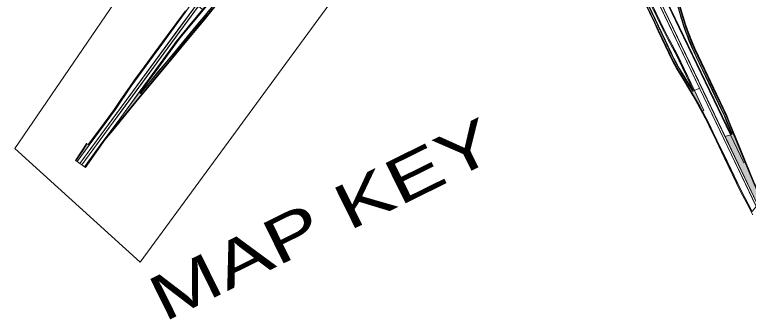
# Model space of a CAD drawing. Extents: x 2356431 to 2371438, y 6972864 to 6982525.
# Drawn here: x 2357864 to 2358220.2, y 6974139.1 to 6974287.2 of the extents above; entities that cross this region are included whole.
import ezdxf

# ---------------------------------------------------------------- set-up
doc = ezdxf.new("R2010")
doc.units = 0
doc.header["$LTSCALE"] = 5.6
for name, color, linetype, lineweight in [('1', 7, 'Continuous', 25), ('10', 7, 'Continuous', 13), ('11', 7, 'Continuous', 13), ('12', 7, 'Continuous', 13), ('13', 7, 'Continuous', 13), ('62', 7, 'Continuous', 25)]:
    doc.layers.add(name, color=color, linetype=linetype, lineweight=lineweight)

msp = doc.modelspace()

# ---------------------------------------------------------------- hatches: boundary and pattern name
at = {"layer": '10'}
for points in [[(2358224.717, 6974194.96), (2358208.937, 6974227.964), (2358211.515, 6974228.83), (2358218.055, 6974215.176), (2358218.638, 6974215.414), (2358222.665, 6974205.55), (2358226.597, 6974197.381)], [(2357893.563, 6974216.383), (2357895.685, 6974219.575), (2357897.226, 6974221.919), (2357898.834, 6974224.657), (2357899.065, 6974224.514), (2357897.698, 6974222.187), (2357896.333, 6974220.089), (2357893.792, 6974216.21)]]:
    msp.add_hatch(color=256, dxfattribs=at).paths.add_polyline_path(points)
at = {"layer": '11'}
for points in [[(2357925.7, 6974248.581), (2357924.467, 6974249.487), (2357915.516, 6974237.29), (2357906.867, 6974225.616)], [(2357899.657, 6974224.163), (2357899.663, 6974224.236), (2357899.684, 6974224.061), (2357900.231, 6974223.779), (2357894.37, 6974215.806), (2357893.782, 6974216.225), (2357895.973, 6974219.512), (2357897.045, 6974221.146), (2357897.88, 6974222.577), (2357898.671, 6974223.818), (2357899.091, 6974224.462)]]:
    msp.add_hatch(color=256, dxfattribs=at).paths.add_polyline_path(points)
at = {"layer": '12'}
msp.add_hatch(color=256, dxfattribs=at).paths.add_polyline_path([(2358190.807, 6974276.108), (2358191.907, 6974276.508), (2358191.955, 6974276.382), (2358190.848, 6974275.981)])
at = {"layer": '13'}
for points in [[(2358188.092, 6974284.474), (2358186.811, 6974288.798), (2358185.541, 6974293.103), (2358184.275, 6974297.396), (2358183.011, 6974301.686), (2358181.658, 6974306.215), (2358180.443, 6974310.36), (2358179.165, 6974314.68), (2358177.844, 6974319.167), (2358178.47, 6974319.318), (2358179.711, 6974314.999), (2358181.042, 6974310.533), (2358182.32, 6974306.211), (2358183.579, 6974301.919), (2358184.842, 6974297.591), (2358186.152, 6974293.285), (2358187.409, 6974288.971), (2358188.697, 6974284.671)], [(2358191.615, 6974276.261), (2358190.083, 6974280.403), (2358188.697, 6974284.671), (2358188.092, 6974284.474), (2358189.441, 6974280.321), (2358190.097, 6974278.481), (2358191.018, 6974276.049)], [(2358206.849, 6974243.48), (2358204.316, 6974248.759), (2358202.039, 6974253.505), (2358200.843, 6974256.042), (2358199.706, 6974258.405), (2358198.739, 6974260.444), (2358198.431, 6974261.097), (2358197.262, 6974263.526), (2358196.947, 6974264.198), (2358194.587, 6974269.146), (2358193.682, 6974271.143), (2358192.779, 6974273.301), (2358191.615, 6974276.261), (2358191.018, 6974276.049), (2358191.605, 6974274.534), (2358192.487, 6974272.368), (2358194.056, 6974268.828), (2358194.955, 6974266.891), (2358197.368, 6974261.863), (2358199.857, 6974256.62), (2358201.785, 6974252.602), (2358204.121, 6974247.695), (2358205.16, 6974245.532), (2358207.016, 6974241.658), (2358208.14, 6974239.202), (2358208.739, 6974239.437)], [(2358187.364, 6974258.405), (2358189.116, 6974255.565), (2358192.039, 6974250.69), (2358194.6, 6974246.247), (2358196.629, 6974242.689), (2358197.823, 6974240.502), (2358197.918, 6974240.283), (2358198.657, 6974240.628), (2358194.012, 6974250.377), (2358193.192, 6974249.987), (2358190.49, 6974254.441), (2358187.921, 6974258.702)], [(2358208.14, 6974239.202), (2358208.77, 6974237.788), (2358209.583, 6974235.939), (2358210.039, 6974234.811), (2358212.325, 6974229.219), (2358211.515, 6974228.83), (2358218.055, 6974215.176), (2358218.638, 6974215.414), (2358212.882, 6974229.514), (2358210.848, 6974234.505), (2358209.364, 6974238.035), (2358208.739, 6974239.437)]]:
    msp.add_hatch(color=256, dxfattribs=at).paths.add_polyline_path(points)

# ---------------------------------------------------------------- linework, layer by layer
at = {"layer": '1', "lineweight": 13}
msp.add_lwpolyline([(2357864.034, 6974222.186), (2358026.863, 6974460.681), (2358031.311, 6974671.634), (2358108.425, 6974690.15), (2358128.625, 6974445.163), (2357925.008, 6974166.994)], close=True, dxfattribs=at)
at = {"layer": '10'}
for points in [[(2358010.915, 6974373.717), (2358012.268, 6974375.13), (2358013.679, 6974376.599), (2358016.224, 6974379.189), (2358007.461, 6974367.185), (2358000.024, 6974357.06), (2357895.642, 6974214.803), (2357894.37, 6974215.806), (2357900.231, 6974223.779), (2357912.964, 6974241.147), (2357920.525, 6974252.361), (2357946.84, 6974288.246), (2357953.979, 6974298.419), (2357959.607, 6974307.178), (2357960.598, 6974306.665), (2357961.331, 6974306.146)], [(2358223.989, 6974194.055), (2358141.811, 6974365.622), (2358143.439, 6974366.392), (2358148.368, 6974355.766), (2358166.699, 6974316.077), (2358175.957, 6974296.873), (2358224.659, 6974195.003)], [(2358211.521, 6974228.879), (2358186.532, 6974280.997), (2358176.917, 6974301.118), (2358174.249, 6974308.244), (2358170.035, 6974319.557), (2358159.816, 6974346.976), (2358158.863, 6974349.564), (2358157.64, 6974352.501), (2358156.781, 6974354.549), (2358152.493, 6974366.759), (2358151.914, 6974367.985), (2358151.794, 6974368.928), (2358152.722, 6974366.988), (2358157.262, 6974354.26), (2358159.629, 6974348.543), (2358160.429, 6974346.368), (2358170.791, 6974318.455), (2358177.306, 6974301.063), (2358184.735, 6974285.539), (2358211.808, 6974229.025)], [(2357895.642, 6974214.801), (2357909.492, 6974233.635), (2357923.388, 6974252.68), (2357943.284, 6974279.759), (2357962.97, 6974306.609), (2357977.718, 6974326.707), (2357989.706, 6974343.023), (2357999.815, 6974356.917), (2358000.336, 6974355.78), (2357993.113, 6974345.51), (2357989.975, 6974340.868), (2357977.162, 6974323.801), (2357960.269, 6974301.043), (2357943.995, 6974278.884), (2357896.621, 6974214.162)], [(2357924.46, 6974249.492), (2357933.957, 6974262.418), (2357943.944, 6974276.001), (2357946.977, 6974279.649), (2357956.31, 6974290.992), (2357965.289, 6974301.865), (2357968.636, 6974305.925), (2357974.763, 6974313.382), (2357978.165, 6974317.738), (2357982.245, 6974323.233), (2357988.087, 6974331.039), (2357988.432, 6974330.792), (2357985.223, 6974326.488), (2357982.696, 6974323.086), (2357977.65, 6974316.366), (2357975.221, 6974313.293), (2357970.27, 6974307.21), (2357964.537, 6974300.258), (2357955.573, 6974289.409), (2357950.091, 6974282.734), (2357944.41, 6974275.854), (2357939.576, 6974269.332), (2357933.994, 6974261.72), (2357924.853, 6974249.264)], [(2358208.937, 6974227.964), (2358200.154, 6974246.303), (2358167.2, 6974315.107), (2358160.678, 6974329.139), (2358164.084, 6974328.195), (2358168.482, 6974318.836), (2358169.553, 6974316.443), (2358173.884, 6974307.403), (2358174.453, 6974307.648), (2358176.918, 6974301.068), (2358211.515, 6974228.83)], [(2358193.196, 6974250.004), (2358191.478, 6974252.884), (2358190.515, 6974254.455), (2358187.741, 6974259.006), (2358184.974, 6974263.852), (2358183.779, 6974266.146), (2358182.955, 6974267.854), (2358179.181, 6974275.801), (2358157.821, 6974320.975), (2358157.98, 6974321.053), (2358182.84, 6974268.477), (2358184.086, 6974265.94), (2358185.149, 6974263.9), (2358186.686, 6974261.126), (2358188.213, 6974258.558), (2358191.295, 6974253.517), (2358193.361, 6974250.086)], [(2358194.012, 6974250.377), (2358185.763, 6974267.596), (2358179.446, 6974279.538), (2358167.386, 6974304.716), (2358166.189, 6974307.26), (2358164.834, 6974309.952), (2358163.579, 6974312.442), (2358162.271, 6974314.907), (2358160.286, 6974318.658), (2358160.839, 6974318.838), (2358161.299, 6974318.676), (2358163.735, 6974319.843), (2358175.31, 6974295.675), (2358196.446, 6974251.544)], [(2357953.269, 6974291.339), (2357927.814, 6974256.688), (2357914.903, 6974239.055), (2357910.465, 6974232.971), (2357896.653, 6974214.174), (2357897.967, 6974213.23), (2357906.867, 6974225.616), (2357915.516, 6974237.29), (2357942.996, 6974274.756), (2357943.999, 6974276.058), (2357948.238, 6974281.244), (2357955.257, 6974289.721)], [(2358212.147, 6974229.139), (2358209.836, 6974234.853), (2358208.581, 6974237.81), (2358207.369, 6974240.52), (2358203.979, 6974247.603), (2358194.854, 6974266.704), (2358193.915, 6974268.717), (2358192.623, 6974271.608), (2358191.557, 6974274.221), (2358190.848, 6974275.986), (2358191.023, 6974276.032), (2358192.05, 6974273.439), (2358193.445, 6974270.156), (2358194.931, 6974266.908), (2358207.078, 6974241.513), (2358208.028, 6974239.437), (2358208.924, 6974237.452), (2358209.816, 6974235.333), (2358210.835, 6974232.855), (2358212.317, 6974229.235)], [(2358226.448, 6974197.447), (2358223.011, 6974204.852), (2358220.385, 6974211.013), (2358218.061, 6974216.864), (2358212.645, 6974230.235), (2358210.538, 6974235.44), (2358207.633, 6974241.864), (2358199.02, 6974259.806), (2358195.526, 6974267.225), (2358193.254, 6974272.36), (2358191.64, 6974276.359), (2358191.981, 6974276.376), (2358194.211, 6974270.921), (2358195.95, 6974267.175), (2358207.919, 6974241.99), (2358209.719, 6974238.124), (2358210.982, 6974235.144), (2358213.014, 6974230.091), (2358216.416, 6974221.838), (2358220.538, 6974211.511), (2358222.763, 6974206.267), (2358226.879, 6974197.787)], [(2358222.074, 6974191.552), (2358216.849, 6974201.441), (2358208.097, 6974219.639), (2358203.977, 6974228.205), (2358203.147, 6974229.944), (2358201.123, 6974234.088), (2358197.918, 6974240.283), (2358198.657, 6974240.628), (2358194.012, 6974250.377), (2358196.446, 6974251.544), (2358205.053, 6974233.57), (2358223.988, 6974194.018)], [(2358224.717, 6974194.96), (2358208.937, 6974227.964), (2358211.515, 6974228.83), (2358218.055, 6974215.176), (2358218.638, 6974215.414), (2358222.665, 6974205.55), (2358226.597, 6974197.381)], [(2357893.563, 6974216.383), (2357895.685, 6974219.575), (2357897.226, 6974221.919), (2357898.834, 6974224.657), (2357899.065, 6974224.514), (2357897.698, 6974222.187), (2357896.333, 6974220.089), (2357893.792, 6974216.21)]]:
    msp.add_lwpolyline(points, close=True, dxfattribs=at)
for points in [[(2358165.05, 6974309.538), (2358179.431, 6974279.534), (2358182.562, 6974273.644), (2358184.569, 6974269.801), (2358186.016, 6974267.047), (2358194.007, 6974250.393), (2358193.605, 6974250.183), (2358186.461, 6974265.122), (2358184.573, 6974268.917), (2358181.17, 6974275.314), (2358178.952, 6974279.541), (2358164.027, 6974310.649)], [(2358168.022, 6974297.81), (2358178.102, 6974276.582), (2358182.082, 6974268.1), (2358184.364, 6974263.595), (2358186.732, 6974259.434), (2358189.402, 6974255.036), (2358191.69, 6974251.275), (2358193.812, 6974247.613), (2358196.236, 6974243.386), (2358199.373, 6974237.518), (2358201.585, 6974233.109), (2358204.95, 6974226.156), (2358204.589, 6974225.978), (2358201.166, 6974233.067), (2358199.297, 6974236.965), (2358195.606, 6974243.821), (2358193.311, 6974247.88), (2358188.982, 6974255.09), (2358186.722, 6974258.749), (2358185.4, 6974261.017), (2358183.469, 6974264.523), (2358181.472, 6974268.636), (2358176.471, 6974279.195), (2358174.585, 6974283.176), (2358169.658, 6974293.631)], [(2357961.219, 6974291.03), (2357955.983, 6974284.513), (2357948.492, 6974275.486), (2357939.168, 6974264.249), (2357930.292, 6974253.587), (2357925.974, 6974248.325), (2357922.91, 6974244.642), (2357912.434, 6974231.868), (2357908.034, 6974226.468), (2357898.338, 6974212.974), (2357897.989, 6974213.237), (2357906.756, 6974225.461), (2357909.359, 6974228.65), (2357910.596, 6974230.179), (2357915.685, 6974236.369), (2357925.715, 6974248.591), (2357932.363, 6974256.639), (2357941.277, 6974267.379), (2357946.757, 6974273.969), (2357956.055, 6974285.172), (2357960.505, 6974290.692)], [(2357947.04, 6974288.525), (2357935.454, 6974272.744), (2357926.159, 6974260.06), (2357920.913, 6974252.92), (2357918.437, 6974249.294), (2357915.292, 6974244.609), (2357912.801, 6974240.886), (2357900.226, 6974223.828), (2357899.752, 6974224.04), (2357904.802, 6974230.757), (2357907.517, 6974234.493), (2357912.414, 6974241.122), (2357915.312, 6974245.411), (2357920.076, 6974252.478), (2357923.088, 6974256.578), (2357926.918, 6974261.817), (2357931.791, 6974268.488), (2357938.106, 6974277.094), (2357946.895, 6974289.074)], [(2357959.791, 6974290.798), (2357956.32, 6974286.497), (2357951.434, 6974280.599), (2357946.495, 6974274.661), (2357936.895, 6974263.086), (2357925.198, 6974248.98), (2357925.065, 6974249.074), (2357927.634, 6974252.165), (2357930.418, 6974255.542), (2357933.613, 6974259.408), (2357935.897, 6974262.135), (2357937.834, 6974264.493), (2357942.516, 6974270.138), (2357952.107, 6974281.683), (2357956.657, 6974287.163), (2357958.591, 6974289.566)], [(2358221.6, 6974192.486), (2358216.977, 6974201.122), (2358215.319, 6974204.68), (2358204.95, 6974226.156), (2358204.589, 6974225.978), (2358208.5, 6974217.786), (2358216.475, 6974201.186), (2358219.611, 6974195.214), (2358222.408, 6974189.975)]]:
    msp.add_lwpolyline(points, dxfattribs=at)
at = {"layer": '11'}
msp.add_lwpolyline([(2357959.891, 6974290.898), (2357954.227, 6974283.961), (2357944.215, 6974271.887), (2357936.509, 6974262.565), (2357925.222, 6974249.014), (2357925.192, 6974248.955), (2357925.7, 6974248.581), (2357933.27, 6974257.699), (2357938.811, 6974264.375), (2357943.482, 6974270.04), (2357948.91, 6974276.56), (2357952.778, 6974281.238), (2357958.554, 6974288.229)], dxfattribs=at)
for points in [[(2357925.7, 6974248.581), (2357924.467, 6974249.487), (2357915.516, 6974237.29), (2357906.867, 6974225.616)], [(2357899.657, 6974224.163), (2357899.663, 6974224.236), (2357899.684, 6974224.061), (2357900.231, 6974223.779), (2357894.37, 6974215.806), (2357893.782, 6974216.225), (2357895.973, 6974219.512), (2357897.045, 6974221.146), (2357897.88, 6974222.577), (2357898.671, 6974223.818), (2357899.091, 6974224.462)]]:
    msp.add_lwpolyline(points, close=True, dxfattribs=at)
at = {"layer": '12'}
for points in [[(2358190.807, 6974276.108), (2358189.899, 6974278.559), (2358189.286, 6974280.279), (2358188.628, 6974282.243), (2358187.927, 6974284.44), (2358187.659, 6974285.309), (2358187.483, 6974285.914), (2358186.605, 6974288.889), (2358164.66, 6974363.278), (2358164.833, 6974363.33), (2358187.656, 6974285.965), (2358188.275, 6974283.967), (2358188.932, 6974281.874), (2358189.944, 6974278.974), (2358190.327, 6974277.811), (2358190.981, 6974276.156)], [(2358191.907, 6974276.508), (2358191.138, 6974278.544), (2358189.91, 6974282.131), (2358188.606, 6974286.244), (2358178.072, 6974321.949), (2358178.074, 6974321.944), (2358167.558, 6974362.806), (2358167.218, 6974362.709), (2358177.725, 6974321.854), (2358184.571, 6974298.546), (2358188.261, 6974286.143), (2358188.813, 6974284.25), (2358189.854, 6974281.097), (2358190.553, 6974279.103), (2358190.944, 6974278.041), (2358191.298, 6974277.097), (2358191.521, 6974276.507), (2358191.569, 6974276.381)], [(2358190.807, 6974276.108), (2358191.907, 6974276.508), (2358191.955, 6974276.382), (2358190.848, 6974275.981)]]:
    msp.add_lwpolyline(points, close=True, dxfattribs=at)
at = {"layer": '13'}
msp.add_lwpolyline([(2358171.162, 6974291.195), (2358182.107, 6974268.136), (2358183.879, 6974264.562), (2358185.264, 6974261.996), (2358187.001, 6974259.011), (2358187.364, 6974258.405), (2358187.921, 6974258.702), (2358186.122, 6974261.792), (2358184.133, 6974265.346), (2358182.676, 6974268.405), (2358182.676, 6974268.405), (2358157.975, 6974320.644)], dxfattribs=at)
for points in [[(2358188.092, 6974284.474), (2358186.811, 6974288.798), (2358185.541, 6974293.103), (2358184.275, 6974297.396), (2358183.011, 6974301.686), (2358181.658, 6974306.215), (2358180.443, 6974310.36), (2358179.165, 6974314.68), (2358177.844, 6974319.167), (2358178.47, 6974319.318), (2358179.711, 6974314.999), (2358181.042, 6974310.533), (2358182.32, 6974306.211), (2358183.579, 6974301.919), (2358184.842, 6974297.591), (2358186.152, 6974293.285), (2358187.409, 6974288.971), (2358188.697, 6974284.671)], [(2358191.615, 6974276.261), (2358190.083, 6974280.403), (2358188.697, 6974284.671), (2358188.092, 6974284.474), (2358189.441, 6974280.321), (2358190.097, 6974278.481), (2358191.018, 6974276.049)], [(2358206.849, 6974243.48), (2358204.316, 6974248.759), (2358202.039, 6974253.505), (2358200.843, 6974256.042), (2358199.706, 6974258.405), (2358198.739, 6974260.444), (2358198.431, 6974261.097), (2358197.262, 6974263.526), (2358196.947, 6974264.198), (2358194.587, 6974269.146), (2358193.682, 6974271.143), (2358192.779, 6974273.301), (2358191.615, 6974276.261), (2358191.018, 6974276.049), (2358191.605, 6974274.534), (2358192.487, 6974272.368), (2358194.056, 6974268.828), (2358194.955, 6974266.891), (2358197.368, 6974261.863), (2358199.857, 6974256.62), (2358201.785, 6974252.602), (2358204.121, 6974247.695), (2358205.16, 6974245.532), (2358207.016, 6974241.658), (2358208.14, 6974239.202), (2358208.739, 6974239.437)], [(2358187.364, 6974258.405), (2358189.116, 6974255.565), (2358192.039, 6974250.69), (2358194.6, 6974246.247), (2358196.629, 6974242.689), (2358197.823, 6974240.502), (2358197.918, 6974240.283), (2358198.657, 6974240.628), (2358194.012, 6974250.377), (2358193.192, 6974249.987), (2358190.49, 6974254.441), (2358187.921, 6974258.702)], [(2358208.14, 6974239.202), (2358208.77, 6974237.788), (2358209.583, 6974235.939), (2358210.039, 6974234.811), (2358212.325, 6974229.219), (2358211.515, 6974228.83), (2358218.055, 6974215.176), (2358218.638, 6974215.414), (2358212.882, 6974229.514), (2358210.848, 6974234.505), (2358209.364, 6974238.035), (2358208.739, 6974239.437)]]:
    msp.add_lwpolyline(points, close=True, dxfattribs=at)

# ---------------------------------------------------------------- texts
at = {"layer": '62', "width": 1.4}
msp.add_text('MAP KEY', height=21.87, rotation=26.268, dxfattribs=at).set_placement((2357936.538, 6974137.648))

doc.saveas('drawing.dxf')
